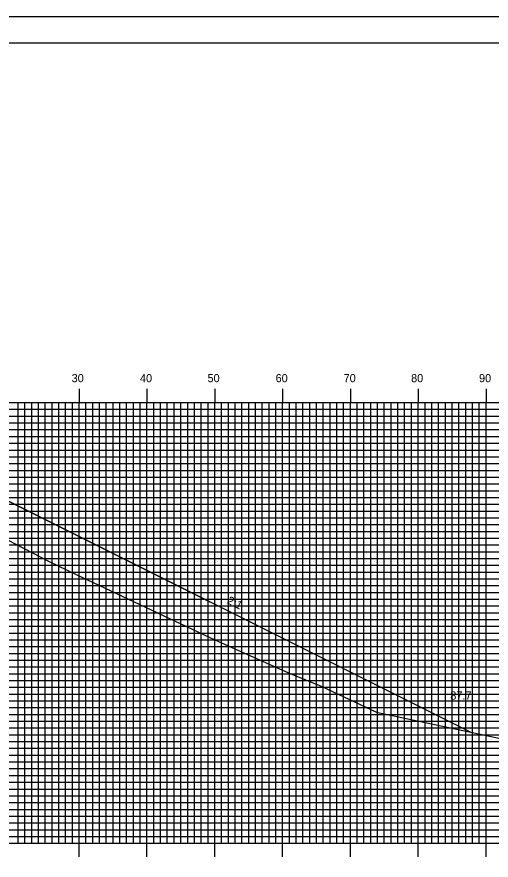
# Model space of a CAD drawing. Extents: x 858684 to 859027, y 364765 to 364985.
# Drawn here: x 858870.7 to 858940.6, y 364860.8 to 364985.2 of the extents above; entities that cross this region are included whole.
import ezdxf

# ---------------------------------------------------------------- set-up
doc = ezdxf.new("R2010")
doc.units = 0
for name, color, linetype in [('ANNOTATION', 7, 'Continuous'), ('BORDER', 7, 'Continuous'), ('D_Roadway_Centerline', 7, 'Continuous'), ('D_Roadway_SlopeLines', 7, 'Continuous'), ('D_Text_Standard', 7, 'Continuous'), ('H_V ANNOTATION', 7, 'Continuous'), ('MAJOR', 7, 'Continuous'), ('MINOR', 7, 'Continuous'), ('PLOT BOUNDARY', 7, 'Continuous'), ('S_Roadway_Centerline', 7, 'Continuous')]:
    doc.layers.add(name, color=color, linetype=linetype)

msp = doc.modelspace()

# ---------------------------------------------------------------- linework, layer by layer
at = {"layer": 'BORDER'}
msp.add_lwpolyline([(858700.25, 364771.3), (859020.25, 364771.3), (859020.25, 364981.3), (858700.25, 364981.3)], close=True, dxfattribs=at)
at = {"layer": 'D_Roadway_Centerline'}
msp.add_lwpolyline([(858817.67, 364915.94), (858817.67, 364915.94), (858820.77, 364916.72), (858827.85, 364918.49), (858827.85, 364918.49), (858828.43, 364918.51), (858830.85, 364918.61), (858830.85, 364918.61), (858835.84, 364918.81), (858835.85, 364918.81), (858835.86, 364918.81), (858844.12, 364918.62), (858849.85, 364918.48), (858849.86, 364918.48), (858854.5, 364918.3), (858857.85, 364918.16), (858857.85, 364918.16), (858858.88, 364918.12), (858860.85, 364918.04), (858865.14, 364915.9), (858865.69, 364915.62), (858865.7, 364915.62), (858937.52, 364879.71)], dxfattribs=at)
at = {"layer": 'D_Roadway_SlopeLines'}
msp.add_lwpolyline([(858860.85, 364918.04), (858937.52, 364879.71)], dxfattribs=at)
at = {"layer": 'MAJOR'}
for p, q in [((858879.85, 364930.31), (858879.85, 364928.3)), ((858889.85, 364930.31), (858889.85, 364928.3)), ((858899.85, 364930.31), (858899.85, 364928.3)), ((858909.85, 364930.31), (858909.85, 364928.3)), ((858919.85, 364930.31), (858919.85, 364928.3)), ((858929.85, 364930.31), (858929.85, 364928.3)), ((858939.85, 364930.31), (858939.85, 364928.3)), ((858709.85, 364928.3), (858989.85, 364928.3)), ((858709.85, 364928.3), (858989.85, 364928.3)), ((858879.85, 364863.3), (858879.85, 364928.3)), ((858889.85, 364863.3), (858889.85, 364928.3)), ((858899.85, 364863.3), (858899.85, 364928.3)), ((858909.85, 364863.3), (858909.85, 364928.3)), ((858919.85, 364863.3), (858919.85, 364928.3)), ((858929.85, 364863.3), (858929.85, 364928.3)), ((858939.85, 364863.3), (858939.85, 364928.3)), ((858709.85, 364923.3), (858989.85, 364923.3)), ((858709.85, 364918.3), (858989.85, 364918.3)), ((858709.85, 364913.3), (858989.85, 364913.3)), ((858709.85, 364908.3), (858989.85, 364908.3)), ((858709.85, 364903.3), (858989.85, 364903.3)), ((858709.85, 364898.3), (858989.85, 364898.3)), ((858709.85, 364893.3), (858989.85, 364893.3)), ((858709.85, 364888.3), (858989.85, 364888.3)), ((858709.85, 364883.3), (858989.85, 364883.3)), ((858709.85, 364878.3), (858989.85, 364878.3)), ((858709.85, 364873.3), (858989.85, 364873.3)), ((858709.85, 364868.3), (858989.85, 364868.3)), ((858709.85, 364863.3), (858989.85, 364863.3)), ((858709.85, 364863.3), (858989.85, 364863.3)), ((858879.85, 364861.3), (858879.85, 364863.3)), ((858889.85, 364861.3), (858889.85, 364863.3)), ((858899.85, 364861.3), (858899.85, 364863.3)), ((858909.85, 364861.3), (858909.85, 364863.3)), ((858919.85, 364861.3), (858919.85, 364863.3)), ((858929.85, 364861.3), (858929.85, 364863.3)), ((858939.85, 364861.3), (858939.85, 364863.3))]:
    msp.add_line(p, q, dxfattribs=at)
at = {"layer": 'MINOR'}
for p, q in [((858870.85, 364863.3), (858870.85, 364928.3)), ((858871.85, 364863.3), (858871.85, 364928.3)), ((858872.85, 364863.3), (858872.85, 364928.3)), ((858873.85, 364863.3), (858873.85, 364928.3)), ((858874.85, 364863.3), (858874.85, 364928.3)), ((858875.85, 364863.3), (858875.85, 364928.3)), ((858876.85, 364863.3), (858876.85, 364928.3)), ((858877.85, 364863.3), (858877.85, 364928.3)), ((858878.85, 364863.3), (858878.85, 364928.3)), ((858880.85, 364863.3), (858880.85, 364928.3)), ((858881.85, 364863.3), (858881.85, 364928.3)), ((858882.85, 364863.3), (858882.85, 364928.3)), ((858883.85, 364863.3), (858883.85, 364928.3)), ((858884.85, 364863.3), (858884.85, 364928.3)), ((858885.85, 364863.3), (858885.85, 364928.3)), ((858886.85, 364863.3), (858886.85, 364928.3)), ((858887.85, 364863.3), (858887.85, 364928.3)), ((858888.85, 364863.3), (858888.85, 364928.3)), ((858890.85, 364863.3), (858890.85, 364928.3)), ((858891.85, 364863.3), (858891.85, 364928.3)), ((858892.85, 364863.3), (858892.85, 364928.3)), ((858893.85, 364863.3), (858893.85, 364928.3)), ((858894.85, 364863.3), (858894.85, 364928.3)), ((858895.85, 364863.3), (858895.85, 364928.3)), ((858896.85, 364863.3), (858896.85, 364928.3)), ((858897.85, 364863.3), (858897.85, 364928.3)), ((858898.85, 364863.3), (858898.85, 364928.3)), ((858900.85, 364863.3), (858900.85, 364928.3)), ((858901.85, 364863.3), (858901.85, 364928.3)), ((858902.85, 364863.3), (858902.85, 364928.3)), ((858903.85, 364863.3), (858903.85, 364928.3)), ((858904.85, 364863.3), (858904.85, 364928.3)), ((858905.85, 364863.3), (858905.85, 364928.3)), ((858906.85, 364863.3), (858906.85, 364928.3)), ((858907.85, 364863.3), (858907.85, 364928.3)), ((858908.85, 364863.3), (858908.85, 364928.3)), ((858910.85, 364863.3), (858910.85, 364928.3)), ((858911.85, 364863.3), (858911.85, 364928.3)), ((858912.85, 364863.3), (858912.85, 364928.3)), ((858913.85, 364863.3), (858913.85, 364928.3)), ((858914.85, 364863.3), (858914.85, 364928.3)), ((858915.85, 364863.3), (858915.85, 364928.3)), ((858916.85, 364863.3), (858916.85, 364928.3)), ((858917.85, 364863.3), (858917.85, 364928.3)), ((858918.85, 364863.3), (858918.85, 364928.3)), ((858920.85, 364863.3), (858920.85, 364928.3)), ((858921.85, 364863.3), (858921.85, 364928.3)), ((858922.85, 364863.3), (858922.85, 364928.3)), ((858923.85, 364863.3), (858923.85, 364928.3)), ((858924.85, 364863.3), (858924.85, 364928.3)), ((858925.85, 364863.3), (858925.85, 364928.3)), ((858926.85, 364863.3), (858926.85, 364928.3)), ((858927.85, 364863.3), (858927.85, 364928.3)), ((858928.85, 364863.3), (858928.85, 364928.3)), ((858930.85, 364863.3), (858930.85, 364928.3)), ((858931.85, 364863.3), (858931.85, 364928.3)), ((858932.85, 364863.3), (858932.85, 364928.3)), ((858933.85, 364863.3), (858933.85, 364928.3)), ((858934.85, 364863.3), (858934.85, 364928.3)), ((858935.85, 364863.3), (858935.85, 364928.3)), ((858936.85, 364863.3), (858936.85, 364928.3)), ((858937.85, 364863.3), (858937.85, 364928.3)), ((858938.85, 364863.3), (858938.85, 364928.3)), ((858709.85, 364927.3), (858989.85, 364927.3)), ((858709.85, 364926.3), (858989.85, 364926.3)), ((858709.85, 364925.3), (858989.85, 364925.3)), ((858709.85, 364924.3), (858989.85, 364924.3)), ((858709.85, 364922.3), (858989.85, 364922.3)), ((858709.85, 364921.3), (858989.85, 364921.3)), ((858709.85, 364920.3), (858989.85, 364920.3)), ((858709.85, 364919.3), (858989.85, 364919.3)), ((858709.85, 364917.3), (858989.85, 364917.3)), ((858709.85, 364916.3), (858989.85, 364916.3)), ((858709.85, 364915.3), (858989.85, 364915.3)), ((858709.85, 364914.3), (858989.85, 364914.3)), ((858709.85, 364912.3), (858989.85, 364912.3)), ((858709.85, 364911.3), (858989.85, 364911.3)), ((858709.85, 364910.3), (858989.85, 364910.3)), ((858709.85, 364909.3), (858989.85, 364909.3)), ((858709.85, 364907.3), (858989.85, 364907.3)), ((858709.85, 364906.3), (858989.85, 364906.3)), ((858709.85, 364905.3), (858989.85, 364905.3)), ((858709.85, 364904.3), (858989.85, 364904.3)), ((858709.85, 364902.3), (858989.85, 364902.3)), ((858709.85, 364901.3), (858989.85, 364901.3)), ((858709.85, 364900.3), (858989.85, 364900.3)), ((858709.85, 364899.3), (858989.85, 364899.3)), ((858709.85, 364897.3), (858989.85, 364897.3)), ((858709.85, 364896.3), (858989.85, 364896.3)), ((858709.85, 364895.3), (858989.85, 364895.3)), ((858709.85, 364894.3), (858989.85, 364894.3)), ((858709.85, 364892.3), (858989.85, 364892.3)), ((858709.85, 364891.3), (858989.85, 364891.3)), ((858709.85, 364890.3), (858989.85, 364890.3)), ((858709.85, 364889.3), (858989.85, 364889.3)), ((858709.85, 364887.3), (858989.85, 364887.3)), ((858709.85, 364886.3), (858989.85, 364886.3)), ((858709.85, 364885.3), (858989.85, 364885.3)), ((858709.85, 364884.3), (858989.85, 364884.3)), ((858709.85, 364882.3), (858989.85, 364882.3)), ((858709.85, 364881.3), (858989.85, 364881.3)), ((858709.85, 364880.3), (858989.85, 364880.3)), ((858709.85, 364879.3), (858989.85, 364879.3)), ((858709.85, 364877.3), (858989.85, 364877.3)), ((858709.85, 364876.3), (858989.85, 364876.3)), ((858709.85, 364875.3), (858989.85, 364875.3)), ((858709.85, 364874.3), (858989.85, 364874.3)), ((858709.85, 364872.3), (858989.85, 364872.3)), ((858709.85, 364871.3), (858989.85, 364871.3)), ((858709.85, 364870.3), (858989.85, 364870.3)), ((858709.85, 364869.3), (858989.85, 364869.3)), ((858709.85, 364867.3), (858989.85, 364867.3)), ((858709.85, 364866.3), (858989.85, 364866.3)), ((858709.85, 364865.3), (858989.85, 364865.3)), ((858709.85, 364864.3), (858989.85, 364864.3))]:
    msp.add_line(p, q, dxfattribs=at)
at = {"layer": 'PLOT BOUNDARY'}
msp.add_lwpolyline([(858684.06, 364765.18), (859024.06, 364765.18), (859024.06, 364985.18), (858684.06, 364985.18)], close=True, dxfattribs=at)
at = {"layer": 'S_Roadway_Centerline'}
msp.add_lwpolyline([(858791.46, 364917.22), (858801.59, 364917.48), (858818, 364918.14), (858824.58, 364918.58), (858838.64, 364918.92), (858844.05, 364919.02), (858850.88, 364916.87), (858859.4, 364913.15), (858875.43, 364904.86), (858879.29, 364902.99), (858899.1, 364893.63), (858900.38, 364893.08), (858910.71, 364888.45), (858915.53, 364886.48), (858923.68, 364882.65), (858954.04, 364876.19), (858960.9, 364873.39), (858962.43, 364872.98), (858971.15, 364871.85), (858973.79, 364871.77), (858976.66, 364871.57), (858989.85, 364870.79)], dxfattribs=at)

# ---------------------------------------------------------------- texts
at = {"layer": 'ANNOTATION'}
msp.add_text('2:1', height=1.2, rotation=333.4345, dxfattribs=at).set_placement((858901.54, 364898.73))
at = {"layer": 'D_Text_Standard'}
msp.add_text("87.7'", height=1.2, dxfattribs=at).set_placement((858934.58, 364884.49))
at = {"layer": 'H_V ANNOTATION'}
for s, p in [('30', (858878.74, 364931.3)), ('40', (858888.82, 364931.3)), ('50', (858898.78, 364931.3)), ('60', (858908.82, 364931.3)), ('70', (858918.85, 364931.3)), ('80', (858928.8, 364931.3)), ('90', (858938.82, 364931.3))]:
    msp.add_text(s, height=1.2, dxfattribs=at).set_placement(p)

doc.saveas('drawing.dxf')
